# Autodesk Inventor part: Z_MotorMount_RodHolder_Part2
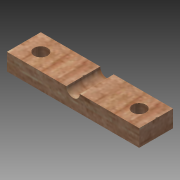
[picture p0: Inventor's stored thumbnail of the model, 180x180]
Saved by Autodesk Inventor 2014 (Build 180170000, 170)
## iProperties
Created: 2013-12
Part Number: Z_MotorMount_RodHolder_Part2
Material: Birch
Document SubType Name: Modeling
Designer: Bram
Density: 0.512 g/cm^3
Appearance: Birch - Natural Medium Gloss
Author: Bram
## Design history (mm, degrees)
sketch "Sketch1"
  geometry: L1 (0, 0)-(78, 0); L2 (78, 0)-(78, 10); L3 (0, 10)-(0, 0); L4 (78, 10)-(43, 10); L5 (35, 10)-(0, 10); A1 r 4 centre (39, 10) between (35, 10) and (43, 10)
  constraints: 10 end point, 3 parallel, 2 point on circle, 1 centre point, 1 horizontal, 1 perpendicular
  dimensions: "d0" = 78 distance of L3.start L2.end; "d1" = 10 distance of L2.end L1.end; "d2" = 8 diameter of A1
extrude "Extrusion1" new body sketch "Sketch1" distance "d3" = 20; taper "d4" = 0 deg
sketch "Sketch2"
  geometry: C1 r 4 at (10, 10); C2 r 4 at (68, 10)
  constraints: 2 centre point
  dimensions: "d7" = 8 diameter of C1; "d8" = 8 diameter of C2
extrude "Extrusion2" cut sketch "Sketch2" distance "d9" = 20; taper "d10" = 0 deg
body "Solid1"
